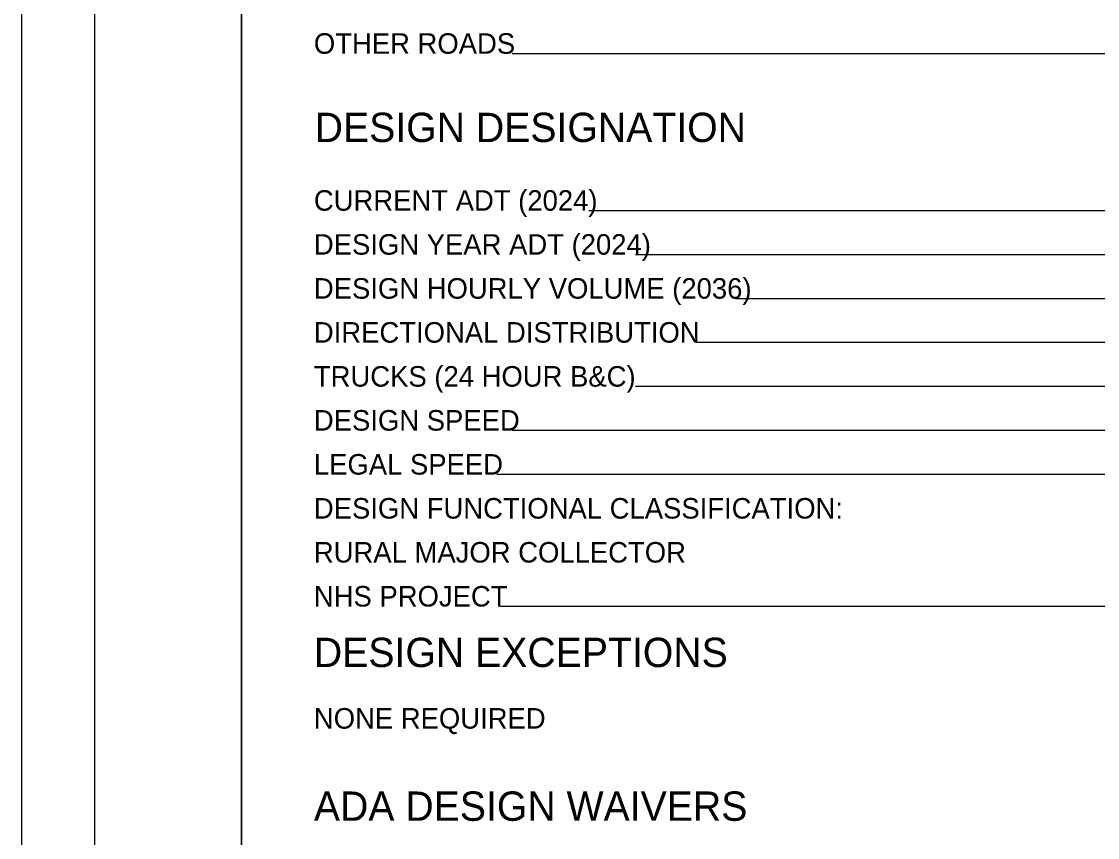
# Model space of a CAD drawing. Extents: x 0 to 45, y -99 to 22.
# Drawn here: x 0 to 7.34, y 5.53 to 11.1 of the extents above; entities that cross this region are included whole.
import ezdxf

# ---------------------------------------------------------------- set-up
doc = ezdxf.new("R2010")
doc.units = 0
for name, color, linetype in [('SH_Border', 7, 'Continuous'), ('SH_Cut_Line', 7, 'Continuous'), ('SH_Data', 7, 'Continuous'), ('SH_Text', 7, 'Continuous')]:
    doc.layers.add(name, color=color, linetype=linetype)

msp = doc.modelspace()

# ---------------------------------------------------------------- linework, layer by layer
at = {"layer": 'SH_Border'}
for points in [[(0.5, 21.5), (1.5, 21.5), (1.5, 0.5), (0.5, 0.5)], [(1.5, 21.5), (33.5, 21.5), (33.5, 0.5), (1.5, 0.5)]]:
    msp.add_lwpolyline(points, close=True, dxfattribs=at)
at = {"layer": 'SH_Cut_Line'}
for p, q in [((7.7, 10.8767), (3.3471, 10.8767)), ((7.6424, 9.8062), (3.871, 9.8062)), ((7.6368, 9.5062), (4.1885, 9.5062)), ((7.6368, 9.2062), (4.8723, 9.2062)), ((7.6368, 8.9062), (4.6037, 8.9062)), ((7.6368, 8.6062), (4.1885, 8.6062)), ((7.6368, 8.3062), (3.346, 8.3062)), ((7.6368, 8.0062), (3.2422, 8.0062)), ((7.6368, 7.1062), (3.2669, 7.1062))]:
    msp.add_line(p, q, dxfattribs=at)
at = {"layer": 'SH_Data'}
msp.add_lwpolyline([(0, 0), (34, 0), (34, 22), (0, 22)], close=True, dxfattribs=at)

# ---------------------------------------------------------------- texts
at = {"layer": 'SH_Cut_Line'}
msp.add_text('DESIGN DESIGNATION', height=0.2, dxfattribs=at).set_placement((2, 10.2747))
at = {"layer": 'SH_Text'}
for s, height, p in [('OTHER ROADS', 0.14, (1.9944, 10.8767)), ('CURRENT ADT (2024)', 0.14, (1.9944, 9.8062)), ('DESIGN YEAR ADT (2024)', 0.14, (1.9944, 9.5062)), ('DESIGN HOURLY VOLUME (2036)', 0.14, (1.9944, 9.2062)), ('DIRECTIONAL DISTRIBUTION', 0.14, (1.9944, 8.9062)), ('TRUCKS (24 HOUR B&C)', 0.14, (1.9944, 8.6062)), ('DESIGN SPEED', 0.14, (1.9944, 8.3062)), ('LEGAL SPEED', 0.14, (1.9944, 8.0062)), ('DESIGN FUNCTIONAL CLASSIFICATION:', 0.14, (1.9944, 7.7062)), ('RURAL MAJOR COLLECTOR                           ', 0.14, (1.9944, 7.4062)), ('NHS PROJECT', 0.14, (1.9944, 7.1062)), ('DESIGN EXCEPTIONS', 0.2, (1.9944, 6.6935)), ('NONE REQUIRED', 0.14, (1.9944, 6.2735)), ('ADA DESIGN WAIVERS', 0.2, (1.9944, 5.6447))]:
    msp.add_text(s, height=height, dxfattribs=at).set_placement(p)

doc.saveas('drawing.dxf')
